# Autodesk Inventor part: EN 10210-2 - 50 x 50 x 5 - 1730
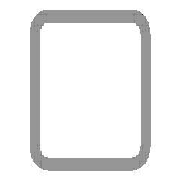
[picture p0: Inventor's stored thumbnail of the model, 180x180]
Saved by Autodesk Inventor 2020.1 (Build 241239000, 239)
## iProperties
IsCustomPart: 1
_CCFamilyMember: 16
_CCFamilyDisplayName: DIN EN 10210-2 (USAS B17.1 quadratisch) - Rohrleitung — In Klammern angegebene Größen wurden aufgehoben
_FrameMemberDoc: Frame Member File
_Version: 15.0.0
_GetPNFromCC: 1
Created: 2019-10
Part Number: EN 10210-2 - 50 x 50 x 5 - 1730
Material: Stahl, weich
Description: Rohrleitung
Document SubType Name: Modeling
Standard: DIN
Designer: lutzd
Standard Revision: 2006-07
Standards Organization: DIN
Language: de-DE
Size Designation: 50 x 50 x 5
Categories: <MemberInstance><Categories><Category DisplayName="Profile" InternalName="089c4875-fa83-4c05-b084-43b9cc11f5ed" Mnemonic="GRDR"><CategoryParameter DisplayName="
Stock Number: 50 x 50 x 5
Mass: 11848.6 g
Surface Area: 5876.65 cm^2
Volume: 1509.38 cm^3
Density: 7.85 g/cm^3
Appearance: Halbpoliert
G_L: 1730,000 mm
G_W: 50,000 mm
G_H: 50,000 mm
Dimensions: 50x50x1730 mm
Mass: 11,849 kg
DocNumber: ADSK-014087
Folder: .
+AF8C09DA-4082-4ACB-BD7D-CEB462B31DDF+SCHNITTDETAIL1: Schnittwinkel 90,00 grd
+CF794175-F005-469F-AD14-8C120BF04E5D+SCHNITTDETAIL2: Schnittwinkel 90,00 grd
Title: Profil-Bauteil
Author: lutzd
Revision Number: -
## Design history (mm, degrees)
node "Startebene"
node "Endebene"
sketch "Skizze"
  geometry: L1 (-25, -17.5)-(-25, 17.5); L2 (-17.5, 25)-(17.5, 25); L3 (25, 17.5)-(25, -17.5); L4 (17.5, -25)-(-17.5, -25); L5 (-15, 20)-(15, 20); L6 (20, 15)-(20, -15); L7 (15, -20)-(-15, -20); L8 (-20, -15)-(-20, 15); L9 (0, 37.175)-(0, -37.175) reference; L10 (-37.175, 0)-(37.175, 0) reference; A1 r 7.5 centre (-17.5, -17.5) between (-25, -17.5) and (-17.5, -25); A2 r 7.5 centre (-17.5, 17.5) between (-17.5, 25) and (-25, 17.5); A3 r 7.5 centre (17.5, 17.5) between (25, 17.5) and (17.5, 25); A4 r 7.5 centre (17.5, -17.5) between (17.5, -25) and (25, -17.5); A5 r 5 centre (-15, -15) between (-20, -15) and (-15, -20); A6 r 5 centre (-15, 15) between (-15, 20) and (-20, 15); A7 r 5 centre (15, 15) between (20, 15) and (15, 20); A8 r 5 centre (15, -15) between (15, -20) and (20, -15)
  constraints: 16 end point, 16 point on circle, 16 tangent, 8 centre point, 6 equal radius, 4 parallel, 2 perpendicular, 2 other
  dimensions: "d7" = 7.5 radius of A1 (= G_IR); "d10" = 50 distance between parallel lines of L2 L4 (= G_H); "d11" = 50 distance between parallel lines of L1 L3 (= G_W); "d12" = 5 distance between parallel lines of L3 L6 (= G_T); "d15" = 25 distance between parallel lines of L2 L10 (= 0.5 x d10); "d16" = 25 distance between parallel lines of L9 L3 (= 0.5 x d11); "d19" = 5 radius of A5 (= G_T); "d20" = 5 distance between parallel lines of L4 L7 (= G_T)
extrude "Körper" new body sketch "Skizze" stored distance "d3" = 1730 (= G_L); taper "d4" = 0 deg
node "Driven Length"
  sketch "Sketch3"
    geometry: L1 (0, 0)-(10, 0) reference
    constraints: 2 end point, 1 horizontal
  workplane "Work Plane3"
  sketch "Sketch4"
    geometry: L1 (-2, 50)-(12, 50) reference; L2 (-2, 1780)-(12, 1780) reference
    dimensions: "d18" = 1730 distance between parallel lines of L1 L2 (derived)
workplane "Arbeitsebene4"
feature "Trennen1"
workplane "Arbeitsebene5"
feature "Trennen2"
sketch "Skizze5"
  geometry: L1 (0, -35)-(0, 0) reference; L2 (0, -17.5)-(921.5, -17.5); 5 further points
  constraints: 3 point on line, 2 end point, 1 coincident, 1 horizontal, 1 midpoint
  dimensions: "d21" = 63.5 distance of point (858, -17.5) point (921.5, -17.5); "d22" = 63.5 distance of point (629.5, -17.5) point (693, -17.5) (= d21); "d23" = 165 distance of point (693, -17.5) point (858, -17.5); "d24" = 629.5 distance from line of point (629.5, -17.5) L1
hole "Bohrung1" sketch "Skizze5" at (921.5, -17.5), (858, -17.5), (693, -17.5), (629.5, -17.5) diameter "d25" = 6.647; stored, may be unused: countersink angle "d29" = 90 deg, drill point angle "d31" = 118 deg; dims "d26" = 16, "d27" = 4, "d28" = 2, "d30" = 8
sketch "Skizze6"
  geometry: L1 (35, 1730)-(0, 1730) reference; L2 (17.5, 1730)-(17.5, 600); 3 further points
  constraints: 2 end point, 2 point on line, 1 midpoint, 1 vertical
  dimensions: "d32" = 115 distance of point (17.5, 715) L2.end; "d33" = 115 distance of point (17.5, 830) point (17.5, 715) (= d32); "d34" = 1130 distance of L2.start L2.end
hole "Bohrung2" sketch "Skizze6" at (17.5, 830), (17.5, 715), (17.5, 600) diameter "d35" = 6.647; stored, may be unused: countersink angle "d39" = 90 deg, drill point angle "d41" = 118 deg; dims "d36" = 16, "d37" = 4, "d38" = 2, "d40" = 8
body "Solid1"
other parameters: "G_W" = 50 [user parameter; used in 1 equation term], "G_H" = 50 [user parameter; used in 1 equation term], "G_T" = 5 [user parameter; used in 3 equation terms], "G_IR" = 7.5 [user parameter; used in 1 equation term], "G_L" = 1730 (= d18) [user parameter; used in 1 equation term], "d17" = 90 deg
